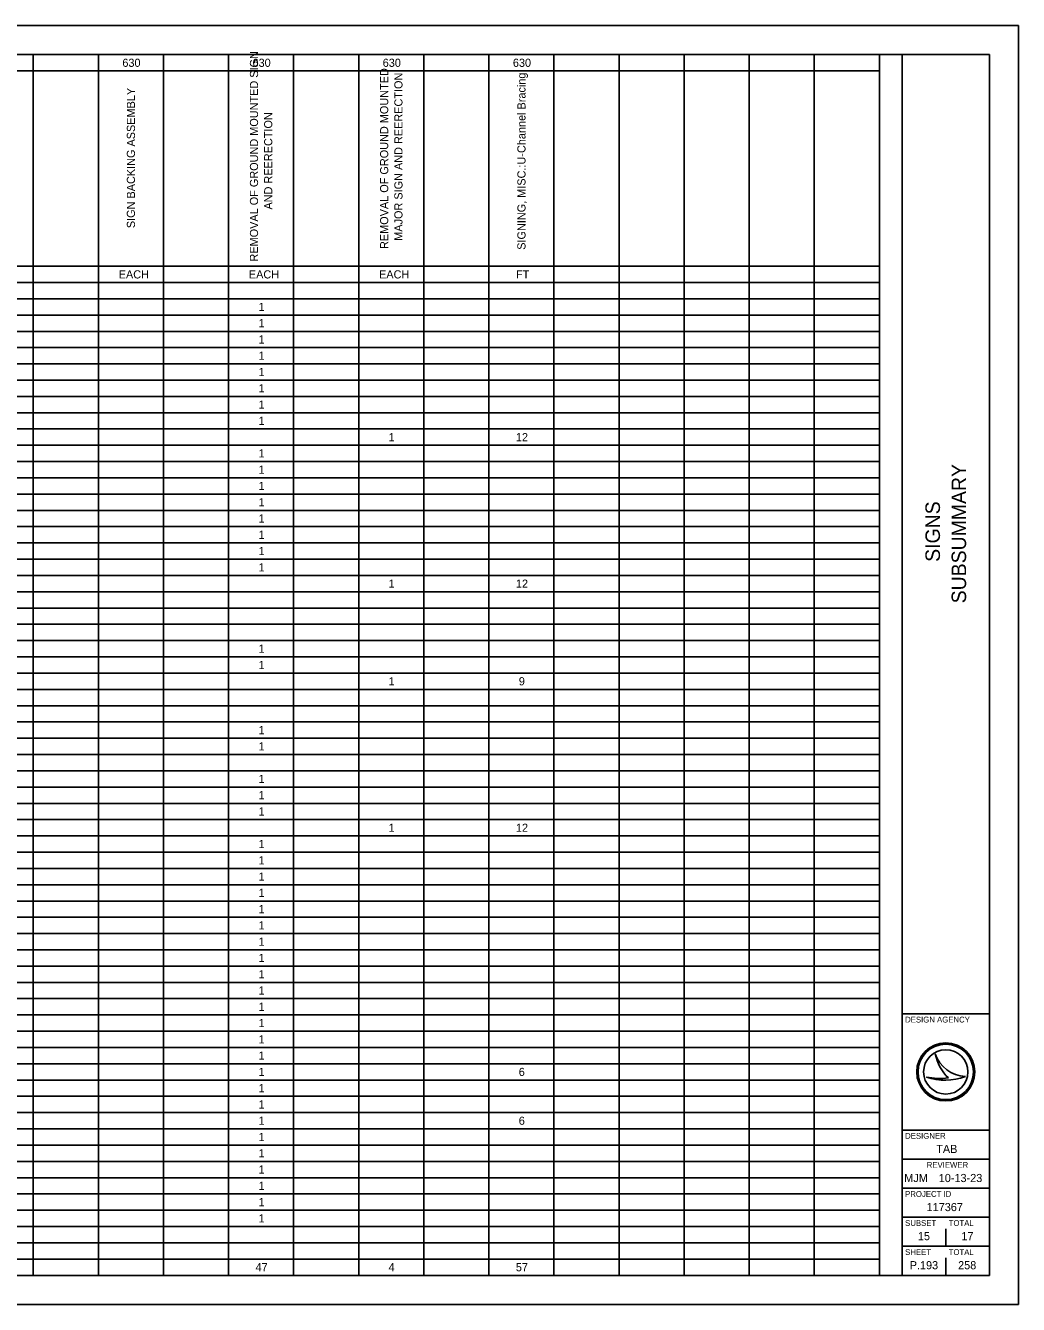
# Model space of a CAD drawing. Extents: x 0 to 34, y 0 to 22.
# Drawn here: x 16.92 to 34, y 0 to 22 of the extents above; entities that cross this region are included whole.
import ezdxf

# ---------------------------------------------------------------- set-up
doc = ezdxf.new("R2010")
doc.units = 0
for name, color, linetype in [('Default', 7, 'Continuous'), ('SH_Border', 7, 'Continuous'), ('SH_Cut_Line', 7, 'Continuous'), ('SH_Data', 7, 'Continuous')]:
    doc.layers.add(name, color=color, linetype=linetype)

msp = doc.modelspace()

# ---------------------------------------------------------------- linework, layer by layer
at = {"layer": 'Default'}
for p, q in [((1.5, 21.5), (31.608, 21.5)), ((17.048, 21.5), (17.048, 0.5)), ((18.168, 21.5), (18.168, 0.5)), ((19.288, 21.5), (19.288, 0.5)), ((20.408, 21.5), (20.408, 0.5)), ((21.528, 21.5), (21.528, 0.5)), ((22.648, 21.5), (22.648, 0.5)), ((23.768, 21.5), (23.768, 0.5)), ((24.888, 21.5), (24.888, 0.5)), ((26.008, 21.5), (26.008, 0.5)), ((27.128, 21.5), (27.128, 0.5)), ((28.248, 21.5), (28.248, 0.5)), ((29.368, 21.5), (29.368, 0.5)), ((30.488, 21.5), (30.488, 0.5)), ((31.608, 21.5), (31.608, 0.5)), ((8.681, 21.22), (31.608, 21.22)), ((8.681, 17.86), (31.608, 17.86)), ((1.5, 17.58), (31.608, 17.58)), ((1.5, 17.3), (31.608, 17.3)), ((1.5, 17.02), (31.608, 17.02)), ((1.5, 16.74), (31.608, 16.74)), ((1.5, 16.46), (31.608, 16.46)), ((1.5, 16.18), (31.608, 16.18)), ((1.5, 15.9), (31.608, 15.9)), ((1.5, 15.62), (31.608, 15.62)), ((1.5, 15.34), (31.608, 15.34)), ((1.5, 15.06), (31.608, 15.06)), ((1.5, 14.78), (31.608, 14.78)), ((1.5, 14.5), (31.608, 14.5)), ((1.5, 14.22), (31.608, 14.22)), ((1.5, 13.94), (31.608, 13.94)), ((1.5, 13.66), (31.608, 13.66)), ((1.5, 13.38), (31.608, 13.38)), ((1.5, 13.1), (31.608, 13.1)), ((1.5, 12.82), (31.608, 12.82)), ((1.5, 12.54), (31.608, 12.54)), ((1.5, 12.26), (31.608, 12.26)), ((1.5, 11.98), (31.608, 11.98)), ((1.5, 11.7), (31.608, 11.7)), ((1.5, 11.42), (31.608, 11.42)), ((1.5, 11.14), (31.608, 11.14)), ((1.5, 10.86), (31.608, 10.86)), ((1.5, 10.58), (31.608, 10.58)), ((1.5, 10.3), (31.608, 10.3)), ((1.5, 10.02), (31.608, 10.02)), ((1.5, 9.74), (31.608, 9.74)), ((1.5, 9.46), (31.608, 9.46)), ((1.5, 9.18), (31.608, 9.18)), ((1.5, 8.9), (31.608, 8.9)), ((1.5, 8.62), (31.608, 8.62)), ((1.5, 8.34), (31.608, 8.34)), ((1.5, 8.06), (31.608, 8.06)), ((1.5, 7.78), (31.608, 7.78)), ((1.5, 7.5), (31.608, 7.5)), ((1.5, 7.22), (31.608, 7.22)), ((1.5, 6.94), (31.608, 6.94)), ((1.5, 6.66), (31.608, 6.66)), ((1.5, 6.38), (31.608, 6.38)), ((1.5, 6.1), (31.608, 6.1)), ((1.5, 5.82), (31.608, 5.82)), ((1.5, 5.54), (31.608, 5.54)), ((1.5, 5.26), (31.608, 5.26)), ((1.5, 4.98), (31.608, 4.98)), ((1.5, 4.7), (31.608, 4.7)), ((1.5, 4.42), (31.608, 4.42)), ((1.5, 4.14), (31.608, 4.14)), ((1.5, 3.86), (31.608, 3.86)), ((1.5, 3.58), (31.608, 3.58)), ((1.5, 3.3), (31.608, 3.3)), ((1.5, 3.02), (31.608, 3.02)), ((1.5, 2.74), (31.608, 2.74)), ((1.5, 2.46), (31.608, 2.46)), ((1.5, 2.18), (31.608, 2.18)), ((1.5, 1.9), (31.608, 1.9)), ((1.5, 1.62), (31.608, 1.62)), ((1.5, 1.34), (31.608, 1.34)), ((1.5, 1.06), (31.608, 1.06)), ((1.5, 0.78), (31.608, 0.78)), ((1.5, 0.5), (31.608, 0.5))]:
    msp.add_line(p, q, dxfattribs=at)
at = {"layer": 'SH_Border'}
for p, q in [((32, 0.5), (32, 21.5)), ((32, 5), (33.5, 5)), ((32, 3), (33.5, 3)), ((32, 2.5), (33.5, 2.5)), ((32, 2), (33.5, 2)), ((32, 1.5), (33.5, 1.5)), ((32, 1), (33.5, 1))]:
    msp.add_line(p, q, dxfattribs=at)
msp.add_lwpolyline([(1.5, 21.5), (33.5, 21.5), (33.5, 0.5), (1.5, 0.5)], close=True, dxfattribs=at)
at = {"layer": 'SH_Cut_Line'}
msp.add_lwpolyline([(0, 0), (34, 0), (34, 22), (0, 22)], close=True, dxfattribs=at)
at = {"layer": 'SH_Data'}
for p, q in [((32.567, 4.31), (32.567, 4.31)), ((32.75, 4), (32.75, 4)), ((32.417, 3.91), (32.417, 3.91)), ((33.087, 3.919), (33.087, 3.919)), ((32.75, 1), (32.75, 1.3)), ((32.375, 0.675), (32.375, 0.675)), ((32.75, 0.5), (32.75, 0.8))]:
    msp.add_line(p, q, dxfattribs=at)
for radius in [0.5, 0.477, 0.477, 0.382]:
    msp.add_circle((32.75, 4), radius, dxfattribs=at)
for centre, radius, start, end in [((33.116, 4.498), 0.58, 198.9257, 198.9319), ((33.347, 4.47), 0.796, 191.6379, 191.6421), ((33.116, 4.498), 0.58, 198.9319, 267.1657), ((33.347, 4.47), 0.796, 191.6421, 226.0947), ((32.739, 4.87), 1.013, 251.4576, 290.0832), ((32.648, 5.154), 1.266, 259.4964, 259.4995), ((32.739, 4.87), 1.013, 251.4527, 251.4576), ((32.648, 5.154), 1.266, 259.4995, 276.6672)]:
    msp.add_arc(centre, radius, start, end, dxfattribs=at)

# ---------------------------------------------------------------- texts
at = {"layer": 'Default'}
for s, p in [('630', (18.581, 21.29)), ('630', (20.821, 21.29)), ('630', (23.061, 21.29)), ('630', (25.301, 21.29)), ('EACH', (18.518, 17.65)), ('EACH', (20.758, 17.65)), ('EACH', (22.998, 17.65)), ('FT', (25.355, 17.65)), ('1', (20.923, 17.09)), ('1', (20.923, 16.81)), ('1', (20.923, 16.53)), ('1', (20.923, 16.25)), ('1', (20.923, 15.97)), ('1', (20.923, 15.69)), ('1', (20.923, 15.41)), ('1', (20.923, 15.13)), ('1', (23.163, 14.85)), ('12', (25.353, 14.85)), ('1', (20.923, 14.57)), ('1', (20.923, 14.29)), ('1', (20.923, 14.01)), ('1', (20.923, 13.73)), ('1', (20.923, 13.45)), ('1', (20.923, 13.17)), ('1', (20.923, 12.89)), ('1', (20.923, 12.61)), ('1', (23.163, 12.33)), ('12', (25.353, 12.33)), ('1', (20.923, 11.21)), ('1', (20.923, 10.93)), ('1', (23.163, 10.65)), ('9', (25.403, 10.65)), ('1', (20.923, 9.81)), ('1', (20.923, 9.53)), ('1', (20.923, 8.97)), ('1', (20.923, 8.69)), ('1', (20.923, 8.41)), ('1', (23.163, 8.13)), ('12', (25.353, 8.13)), ('1', (20.923, 7.85)), ('1', (20.923, 7.57)), ('1', (20.923, 7.29)), ('1', (20.923, 7.01)), ('1', (20.923, 6.73)), ('1', (20.923, 6.45)), ('1', (20.923, 6.17)), ('1', (20.923, 5.89)), ('1', (20.923, 5.61)), ('1', (20.923, 5.33)), ('1', (20.923, 5.05)), ('1', (20.923, 4.77)), ('1', (20.923, 4.49)), ('1', (20.923, 4.21)), ('1', (20.923, 3.93)), ('6', (25.402, 3.93)), ('1', (20.923, 3.65)), ('1', (20.923, 3.37)), ('1', (20.923, 3.09)), ('6', (25.402, 3.09)), ('1', (20.923, 2.81)), ('1', (20.923, 2.53)), ('1', (20.923, 2.25)), ('1', (20.923, 1.97)), ('1', (20.923, 1.69)), ('1', (20.923, 1.41)), ('47', (20.872, 0.57)), ('4', (23.161, 0.57)), ('57', (25.352, 0.57))]:
    msp.add_text(s, height=0.14, dxfattribs=at).set_placement(p)
for s, p in [('REMOVAL OF GROUND MOUNTED SIGN ', (20.916, 17.941)), ('REMOVAL OF GROUND MOUNTED ', (23.156, 18.157)), ('MAJOR SIGN AND REERECTION', (23.401, 18.298)), ('SIGNING, MISC.:U-Channel Bracing', (25.518, 18.143)), ('SIGN BACKING ASSEMBLY', (18.798, 18.515)), ('AND REERECTION', (21.161, 18.835))]:
    msp.add_text(s, height=0.14, rotation=90, dxfattribs=at).set_placement(p)
at = {"layer": 'SH_Data'}
for s, p in [('SUBSUMMARY', (33.1, 12.061)), ('SIGNS', (32.65, 12.775))]:
    msp.add_text(s, height=0.25, rotation=90, dxfattribs=at).set_placement(p)
for s, height, p in [('DESIGN AGENCY', 0.1, (32.05, 4.85)), ('DESIGNER', 0.1, (32.05, 2.85)), ('TAB', 0.14, (32.586, 2.605)), ('REVIEWER', 0.1, (32.422, 2.35)), ('MJM', 0.14, (32.035, 2.105)), ('10-13-23', 0.14, (32.629, 2.105)), ('PROJECT ID', 0.1, (32.05, 1.85)), ('117367', 0.14, (32.42, 1.605)), ('SUBSET', 0.1, (32.05, 1.35)), ('TOTAL', 0.1, (32.8, 1.35)), ('15', 0.14, (32.27, 1.105)), ('17', 0.14, (33.018, 1.105)), ('SHEET', 0.1, (32.05, 0.85)), ('TOTAL', 0.1, (32.8, 0.85)), ('P.193', 0.14, (32.129, 0.605)), ('258', 0.14, (32.962, 0.605))]:
    msp.add_text(s, height=height, dxfattribs=at).set_placement(p)

doc.saveas('drawing.dxf')
